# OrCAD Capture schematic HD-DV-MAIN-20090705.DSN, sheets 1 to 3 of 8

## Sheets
1 A2S- DDR2 & VOUT & GPIO: size A2
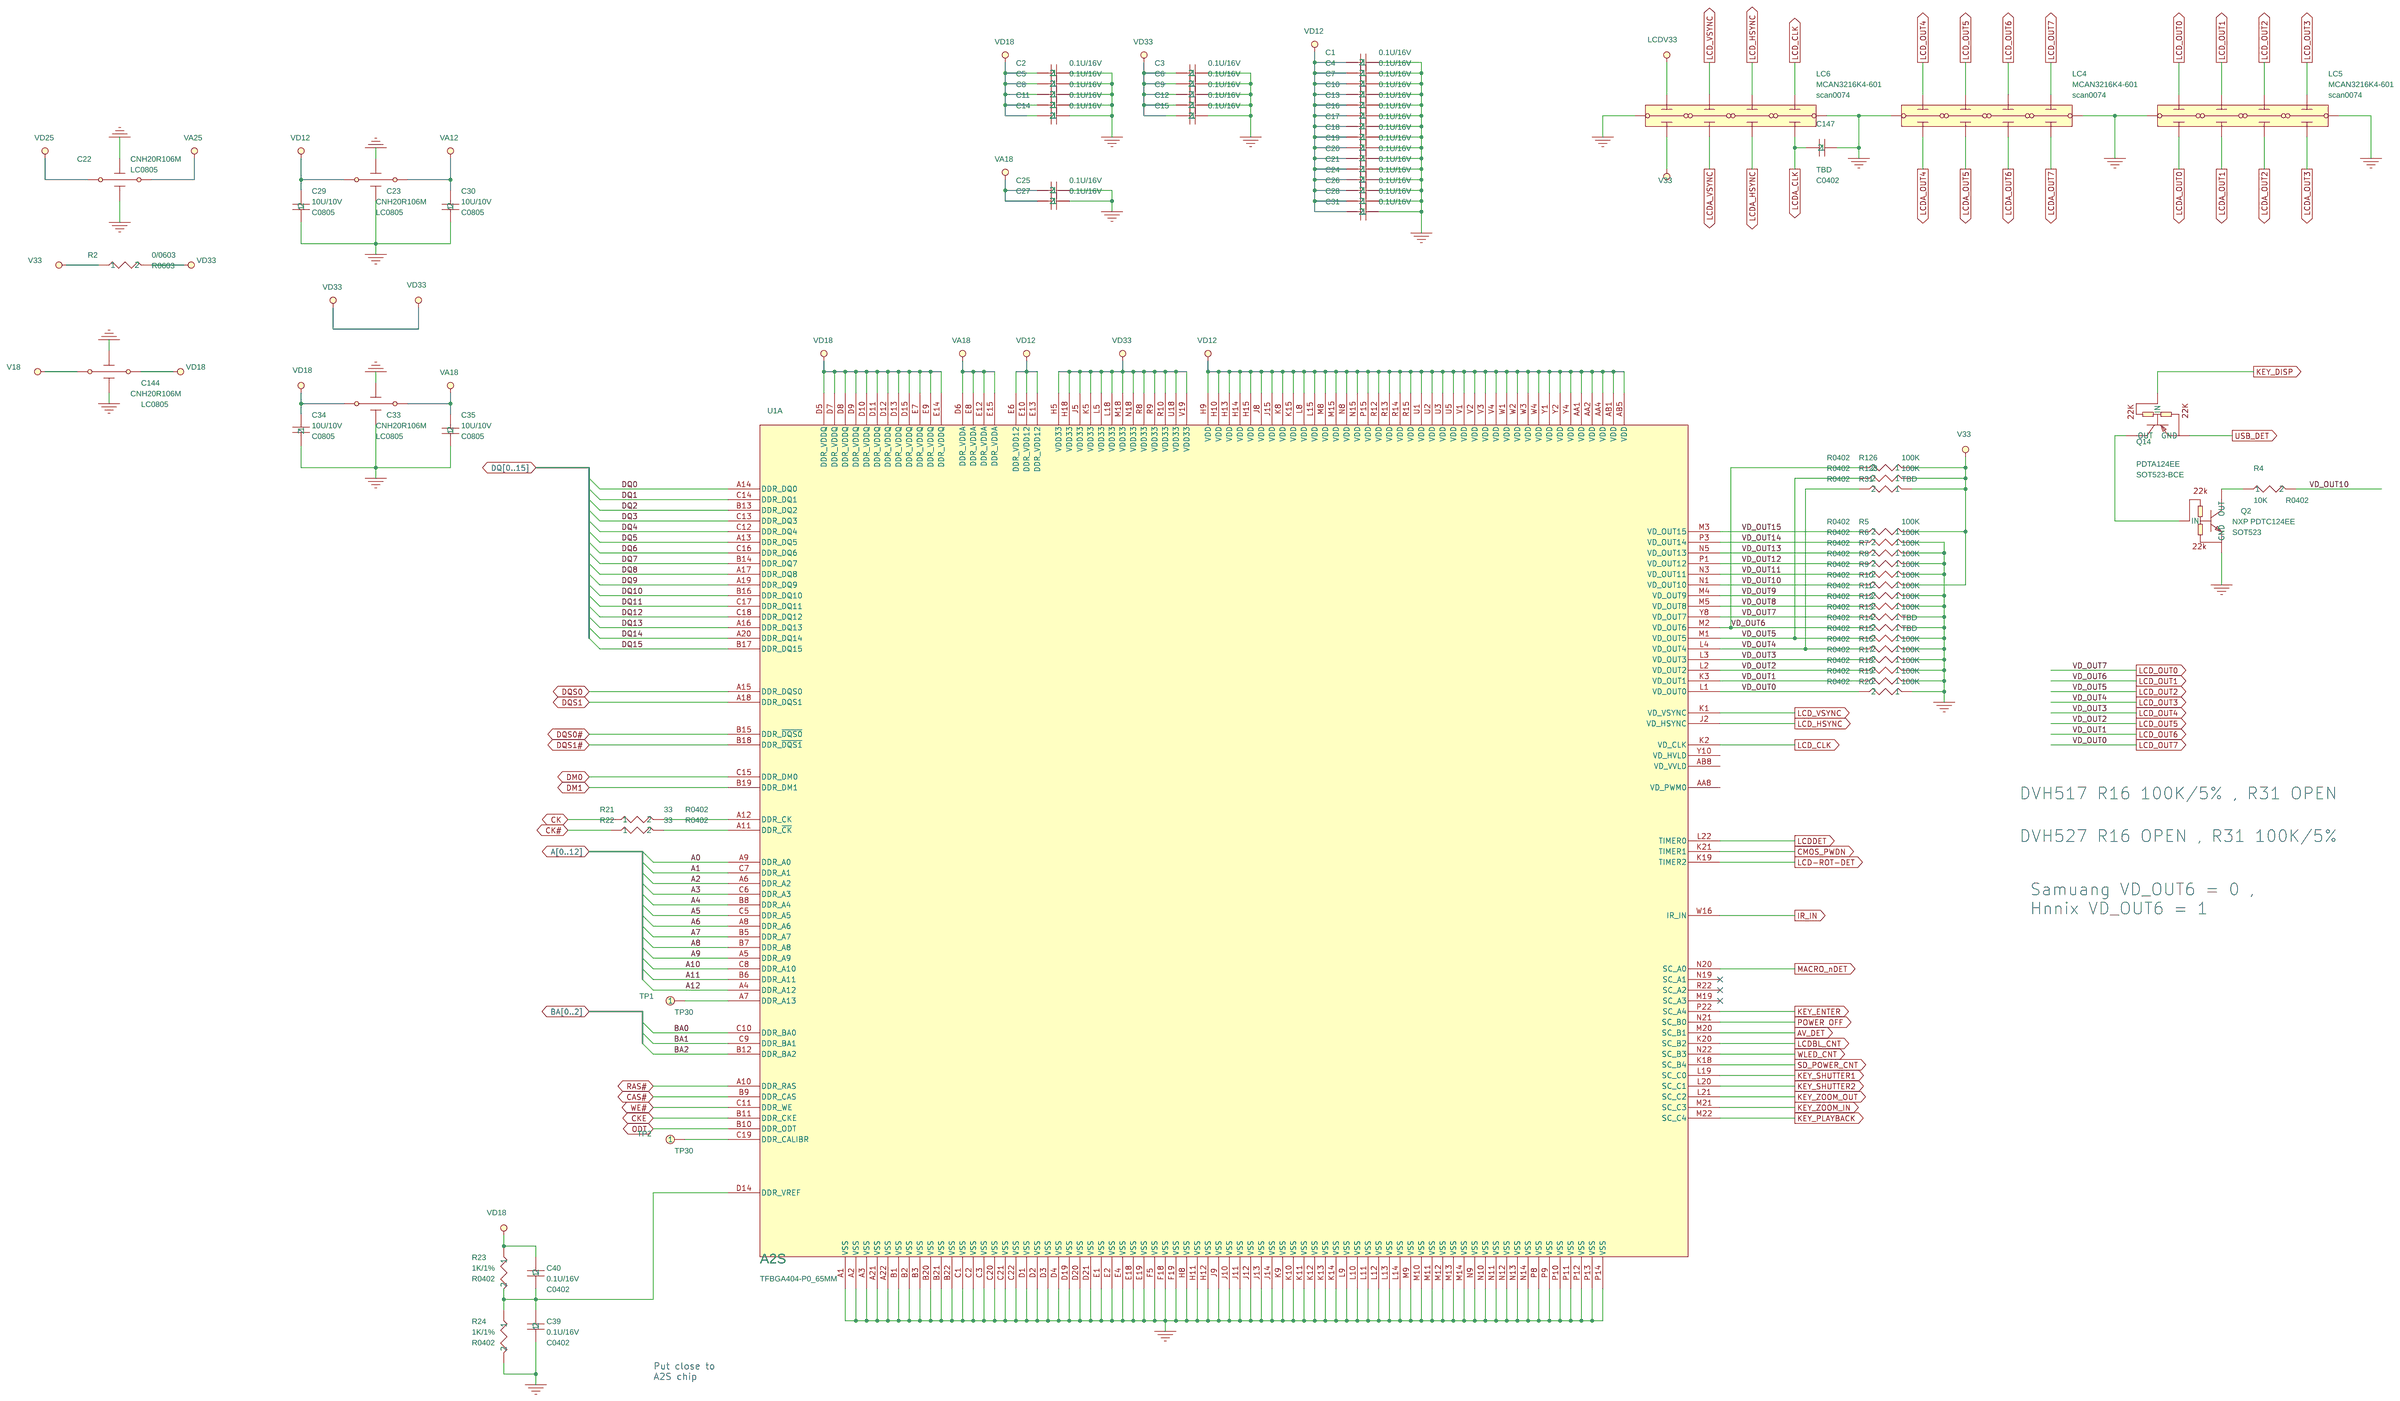
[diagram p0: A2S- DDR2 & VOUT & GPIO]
2 A2S- PWC & HDMI: size A3
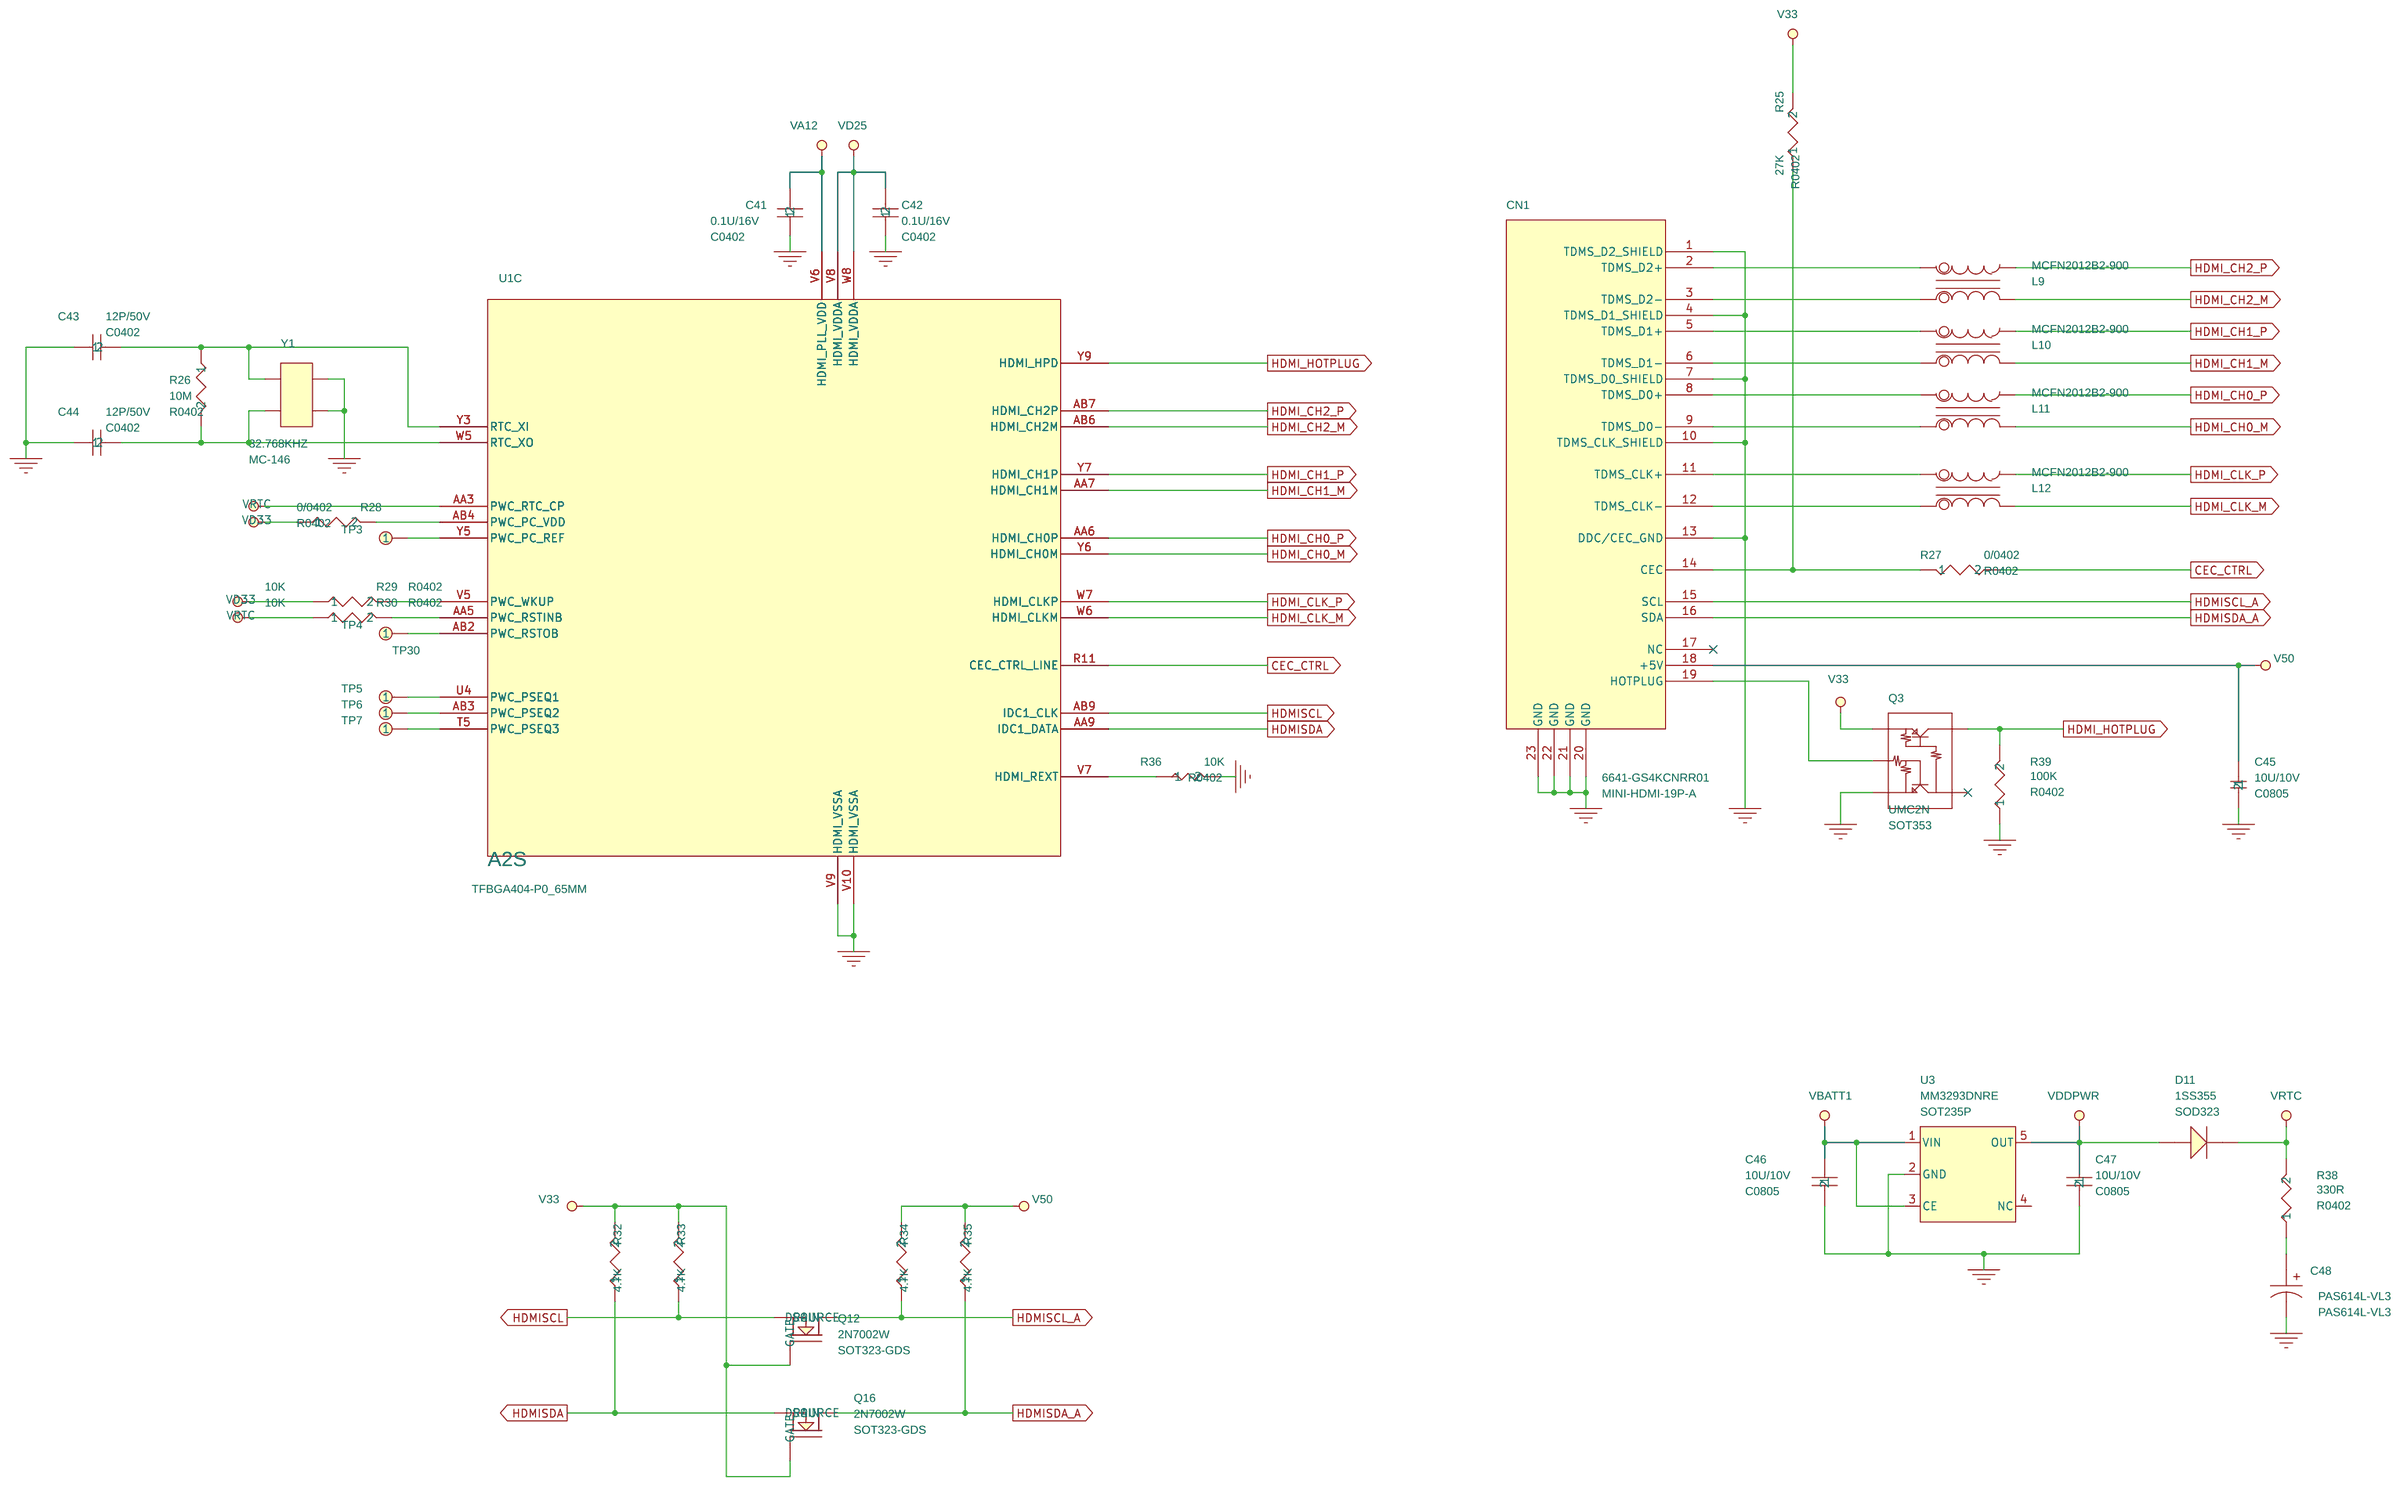
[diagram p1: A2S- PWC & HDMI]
3 A2S- SMIO & VIN& USB & Misc: size A2
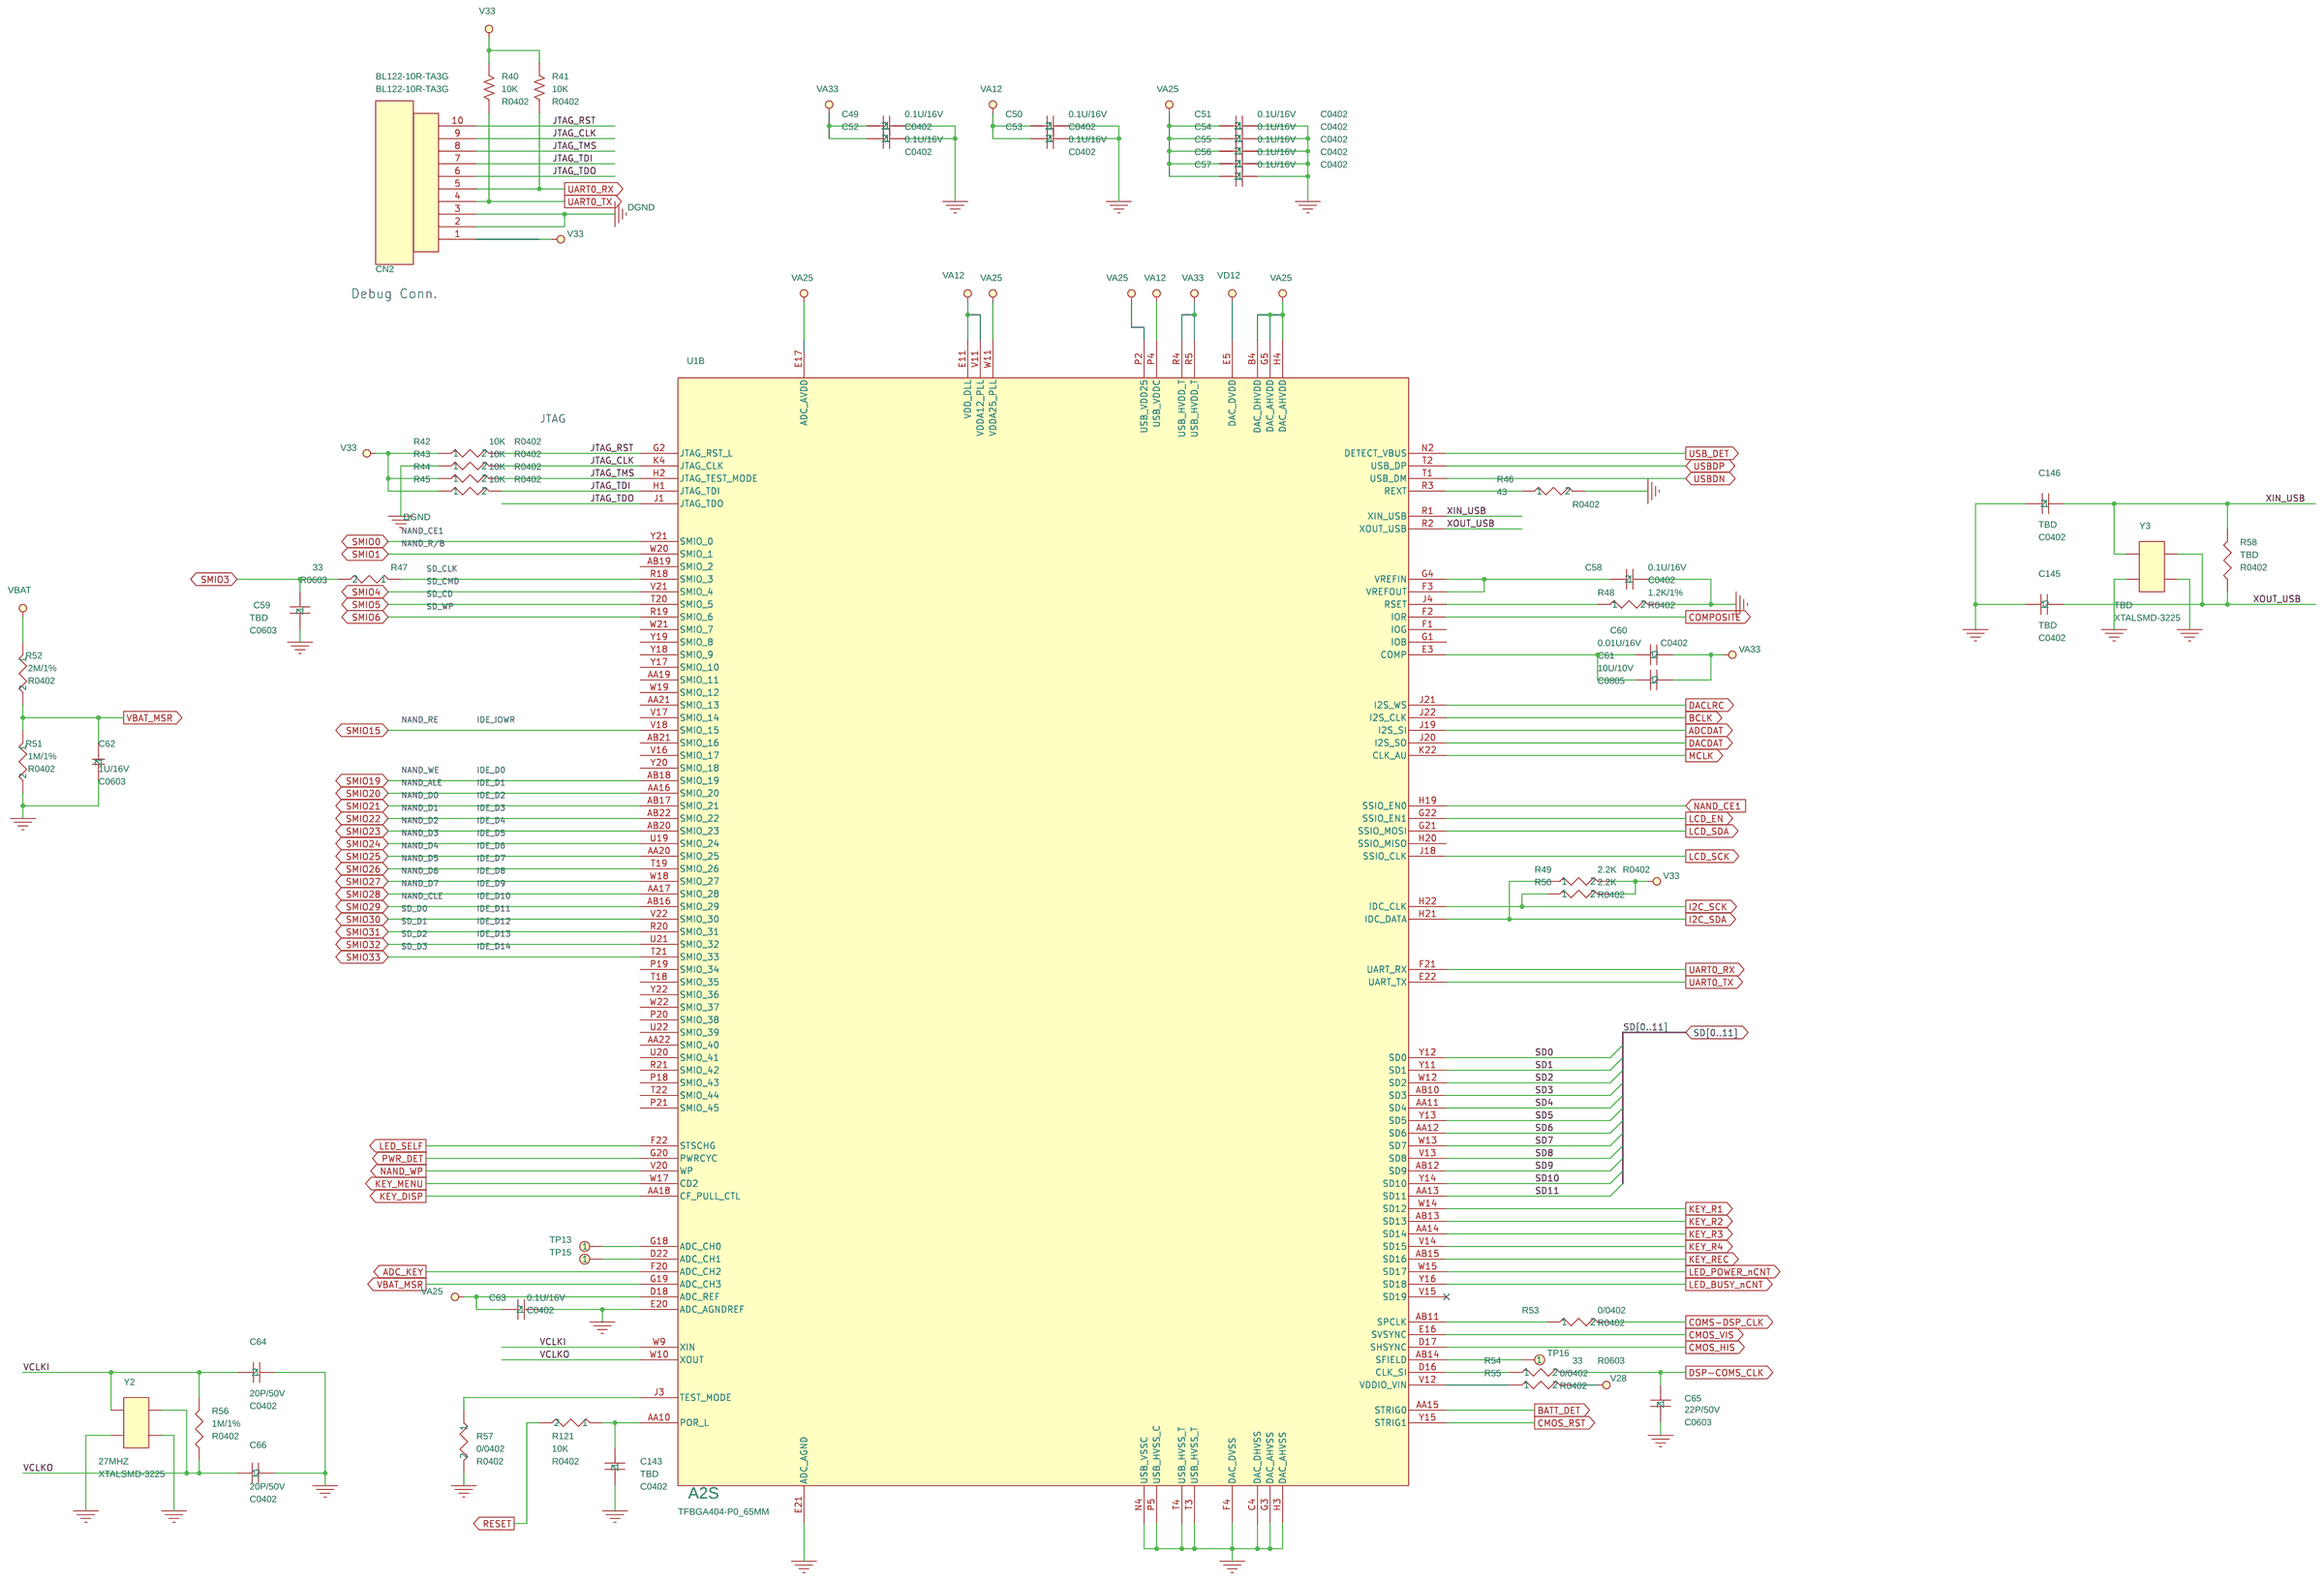
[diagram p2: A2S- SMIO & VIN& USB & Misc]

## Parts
sheet A2S- DDR2 & VOUT & GPIO
C1  0.1U/16V  [C0402]
C2  0.1U/16V  [C0402]
C3  0.1U/16V  [C0402]
C4  0.1U/16V  [C0402]
C5  0.1U/16V  [C0402]
C6  0.1U/16V  [C0402]
C7  0.1U/16V  [C0402]
C8  0.1U/16V  [C0402]
C9  0.1U/16V  [C0402]
C10  0.1U/16V  [C0402]
C11  0.1U/16V  [C0402]
C12  0.1U/16V  [C0402]
C13  0.1U/16V  [C0402]
C14  0.1U/16V  [C0402]
C15  0.1U/16V  [C0402]
C16  0.1U/16V  [C0402]
C17  0.1U/16V  [C0402]
C18  0.1U/16V  [C0402]
C19  0.1U/16V  [C0402]
C20  0.1U/16V  [C0402]
C21  0.1U/16V  [C0402]
C22  CNH20R106M  [LC0805]
C23  CNH20R106M  [LC0805]
C24  0.1U/16V  [C0402]
C25  0.1U/16V  [C0402]
C26  0.1U/16V  [C0402]
C27  0.1U/16V  [C0402]
C28  0.1U/16V  [C0402]
C29  10U/10V  [C0805]
C30  10U/10V  [C0805]
C31  0.1U/16V  [C0402]
C33  CNH20R106M  [LC0805]
C34  10U/10V  [C0805]
C35  10U/10V  [C0805]
C39  0.1U/16V  [C0402]
C40  0.1U/16V  [C0402]
C144  CNH20R106M  [LC0805]
C147  TBD  [C0402]
LC4  MCAN3216K4-601  [scan0074]
LC5  MCAN3216K4-601  [scan0074]
LC6  MCAN3216K4-601  [scan0074]
Q2  NXP PDTC124EE  [SOT523]
Q14  PDTA124EE  [SOT523-BCE]
R2  0/0603  [R0603]
R4  10K  [R0402]
R5  100K  [R0402]
R6  100K  [R0402]
R7  100K  [R0402]
R8  100K  [R0402]
R9  100K  [R0402]
R10  100K  [R0402]
R11  100K  [R0402]
R12  100K  [R0402]
R13  100K  [R0402]
R14  TBD  [R0402]
R15  TBD  [R0402]
R16  100K  [R0402]
R17  100K  [R0402]
R18  100K  [R0402]
R19  100K  [R0402]
R20  100K  [R0402]
R21  33  [R0402]
R22  33  [R0402]
R23  1K/1%  [R0402]
R24  1K/1%  [R0402]
R31  TBD  [R0402]
R123  100K  [R0402]
R126  100K  [R0402]
TP1  TP  [TP30]
TP2  TP  [TP30]
U1  A2S  [TFBGA404-P0_65MM]  (sections A,B,C)
sheet A2S- PWC & HDMI
C41  0.1U/16V  [C0402]
C42  0.1U/16V  [C0402]
C43  12P/50V  [C0402]
C44  12P/50V  [C0402]
C45  10U/10V  [C0805]
C46  10U/10V  [C0805]
C47  10U/10V  [C0805]
C48  PAS614L-VL3  [PAS614L-VL3]
CN1  6641-GS4KCNRR01  [MINI-HDMI-19P-A]
D11  1SS355  [SOD323]
L9  MCFN2012B2-900  [ACM2012]
L10  MCFN2012B2-900  [ACM2012]
L11  MCFN2012B2-900  [ACM2012]
L12  MCFN2012B2-900  [ACM2012]
Q3  UMC2N  [SOT353]
Q12  2N7002W  [SOT323-GDS]
Q16  2N7002W  [SOT323-GDS]
R25  27K  [R0402]
R26  10M  [R0402]
R27  0/0402  [R0402]
R28  0/0402  [R0402]
R29  10K  [R0402]
R30  10K  [R0402]
R32  4.7K  [R0402]
R33  4.7K  [R0402]
R34  4.7K  [R0402]
R35  4.7K  [R0402]
R36  10K  [R0402]
R38  330R  [R0402]
R39  100K  [R0402]
TP3  TP  [TP30]
TP4  TP  [TP30]
TP5  TP  [TP30]
TP6  TP  [TP30]
TP7  TP  [TP30]
U3  MM3293DNRE  [SOT235P]
Y1  32.768KHZ  [MC-146]
sheet A2S- SMIO & VIN& USB & Misc
C49  0.1U/16V  [C0402]
C50  0.1U/16V  [C0402]
C51  0.1U/16V  [C0402]
C52  0.1U/16V  [C0402]
C53  0.1U/16V  [C0402]
C54  0.1U/16V  [C0402]
C55  0.1U/16V  [C0402]
C56  0.1U/16V  [C0402]
C57  0.1U/16V  [C0402]
C58  0.1U/16V  [C0402]
C59  TBD  [C0603]
C60  0.01U/16V  [C0402]
C61  10U/10V  [C0805]
C62  1U/16V  [C0603]
C63  0.1U/16V  [C0402]
C64  20P/50V  [C0402]
C65  22P/50V  [C0603]
C66  20P/50V  [C0402]
C143  TBD  [C0402]
C145  TBD  [C0402]
C146  TBD  [C0402]
CN2  BL122-10R-TA3G  [BL122-10R-TA3G]
R40  10K  [R0402]
R41  10K  [R0402]
R42  10K  [R0402]
R43  10K  [R0402]
R44  10K  [R0402]
R45  10K  [R0402]
R46  43  [R0402]
R47  33  [R0603]
R48  1.2K/1%  [R0402]
R49  2.2K  [R0402]
R50  2.2K  [R0402]
R51  1M/1%  [R0402]
R52  2M/1%  [R0402]
R53  0/0402  [R0402]
R54  33  [R0603]
R55  0/0402  [R0402]
R56  1M/1%  [R0402]
R57  0/0402  [R0402]
R58  TBD  [R0402]
R121  10K  [R0402]
TP13  TP  [TP30]
TP15  TP  [TP30]
TP16  TP  [TP30]
Y2  27MHZ  [XTALSMD-3225]
Y3  TBD  [XTALSMD-3225]

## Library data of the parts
C1 = CAP_NP_2: CHIP CAP,104PZ/16V,0402,Y5V; Approved: Y; BOM Value: 0.1U/16V/X5R/0402; CIS_PART_NUMBER: 24-3E3-10418-000-POE; Manufacturer: POE; Manufacturer's Part Number: B0402F104ZCT; Material: Y5V; PART_TYPE: MLCC; Package Type: 0402; Part Number: 24-3E3-10418-000; Rate Volt: 16V; Tolerance: -20~+80
C2 = CAP_NP_33: CHIP CAP,104PZ/16V,0402,Y5V; Approved: Y; BOM Value: 0.1U/16V/X5R/0402; CIS_PART_NUMBER: 24-3E3-10418-000-POE; Manufacturer: POE; Manufacturer's Part Number: B0402F104ZCT; Material: Y5V; PART_TYPE: MLCC; Package Type: 0402; Part Number: 24-3E3-10418-000; Rate Volt: 16V; Tolerance: -20~+80
C3 = CAP_NP_28: CHIP CAP,104PZ/16V,0402,Y5V; Approved: Y; BOM Value: 0.1U/16V/X5R/0402; CIS_PART_NUMBER: 24-3E3-10418-000-POE; Manufacturer: POE; Manufacturer's Part Number: B0402F104ZCT; Material: Y5V; PART_TYPE: MLCC; Package Type: 0402; Part Number: 24-3E3-10418-000; Rate Volt: 16V; Tolerance: -20~+80
C4 = CAP_NP_11: CHIP CAP,104PZ/16V,0402,Y5V; Approved: Y; BOM Value: 0.1U/16V/X5R/0402; CIS_PART_NUMBER: 24-3E3-10418-000-POE; Manufacturer: POE; Manufacturer's Part Number: B0402F104ZCT; Material: Y5V; PART_TYPE: MLCC; Package Type: 0402; Part Number: 24-3E3-10418-000; Rate Volt: 16V; Tolerance: -20~+80
C5 = CAP_NP_20: CHIP CAP,104PZ/16V,0402,Y5V; Approved: Y; BOM Value: 0.1U/16V/X5R/0402; CIS_PART_NUMBER: 24-3E3-10418-000-POE; Manufacturer: POE; Manufacturer's Part Number: B0402F104ZCT; Material: Y5V; PART_TYPE: MLCC; Package Type: 0402; Part Number: 24-3E3-10418-000; Rate Volt: 16V; Tolerance: -20~+80
C6 = CAP_NP_23: CHIP CAP,104PZ/16V,0402,Y5V; Approved: Y; BOM Value: 0.1U/16V/X5R/0402; CIS_PART_NUMBER: 24-3E3-10418-000-POE; Manufacturer: POE; Manufacturer's Part Number: B0402F104ZCT; Material: Y5V; PART_TYPE: MLCC; Package Type: 0402; Part Number: 24-3E3-10418-000; Rate Volt: 16V; Tolerance: -20~+80
C7 = CAP_NP_19: CHIP CAP,104PZ/16V,0402,Y5V; Approved: Y; BOM Value: 0.1U/16V/X5R/0402; CIS_PART_NUMBER: 24-3E3-10418-000-POE; Manufacturer: POE; Manufacturer's Part Number: B0402F104ZCT; Material: Y5V; PART_TYPE: MLCC; Package Type: 0402; Part Number: 24-3E3-10418-000; Rate Volt: 16V; Tolerance: -20~+80
C8 C56 = CAP_NP_1: CHIP CAP,104PZ/16V,0402,Y5V; Approved: Y; BOM Value: 0.1U/16V/X5R/0402; CIS_PART_NUMBER: 24-3E3-10418-000-POE; Manufacturer: POE; Manufacturer's Part Number: B0402F104ZCT; Material: Y5V; PART_TYPE: MLCC; Package Type: 0402; Part Number: 24-3E3-10418-000; Rate Volt: 16V; Tolerance: -20~+80
C9 = CAP_NP_15: CHIP CAP,104PZ/16V,0402,Y5V; Approved: Y; BOM Value: 0.1U/16V/X5R/0402; CIS_PART_NUMBER: 24-3E3-10418-000-POE; Manufacturer: POE; Manufacturer's Part Number: B0402F104ZCT; Material: Y5V; PART_TYPE: MLCC; Package Type: 0402; Part Number: 24-3E3-10418-000; Rate Volt: 16V; Tolerance: -20~+80
C10 = CAP_NP_22: CHIP CAP,104PZ/16V,0402,Y5V; Approved: Y; BOM Value: 0.1U/16V/X5R/0402; CIS_PART_NUMBER: 24-3E3-10418-000-POE; Manufacturer: POE; Manufacturer's Part Number: B0402F104ZCT; Material: Y5V; PART_TYPE: MLCC; Package Type: 0402; Part Number: 24-3E3-10418-000; Rate Volt: 16V; Tolerance: -20~+80
C11 = CAP_NP_31: CHIP CAP,104PZ/16V,0402,Y5V; Approved: Y; BOM Value: 0.1U/16V/X5R/0402; CIS_PART_NUMBER: 24-3E3-10418-000-POE; Manufacturer: POE; Manufacturer's Part Number: B0402F104ZCT; Material: Y5V; PART_TYPE: MLCC; Package Type: 0402; Part Number: 24-3E3-10418-000; Rate Volt: 16V; Tolerance: -20~+80
C12 = CAP_NP_17: CHIP CAP,104PZ/16V,0402,Y5V; Approved: Y; BOM Value: 0.1U/16V/X5R/0402; CIS_PART_NUMBER: 24-3E3-10418-000-POE; Manufacturer: POE; Manufacturer's Part Number: B0402F104ZCT; Material: Y5V; PART_TYPE: MLCC; Package Type: 0402; Part Number: 24-3E3-10418-000; Rate Volt: 16V; Tolerance: -20~+80
C13 = CAP_NP_12: CHIP CAP,104PZ/16V,0402,Y5V; Approved: Y; BOM Value: 0.1U/16V/X5R/0402; CIS_PART_NUMBER: 24-3E3-10418-000-POE; Manufacturer: POE; Manufacturer's Part Number: B0402F104ZCT; Material: Y5V; PART_TYPE: MLCC; Package Type: 0402; Part Number: 24-3E3-10418-000; Rate Volt: 16V; Tolerance: -20~+80
C14 = CAP_NP_21: CHIP CAP,104PZ/16V,0402,Y5V; Approved: Y; BOM Value: 0.1U/16V/X5R/0402; CIS_PART_NUMBER: 24-3E3-10418-000-POE; Manufacturer: POE; Manufacturer's Part Number: B0402F104ZCT; Material: Y5V; PART_TYPE: MLCC; Package Type: 0402; Part Number: 24-3E3-10418-000; Rate Volt: 16V; Tolerance: -20~+80
C15 = CAP_NP_25: CHIP CAP,104PZ/16V,0402,Y5V; Approved: Y; BOM Value: 0.1U/16V/X5R/0402; CIS_PART_NUMBER: 24-3E3-10418-000-POE; Manufacturer: POE; Manufacturer's Part Number: B0402F104ZCT; Material: Y5V; PART_TYPE: MLCC; Package Type: 0402; Part Number: 24-3E3-10418-000; Rate Volt: 16V; Tolerance: -20~+80
C16 C57 = CAP_NP_13: CHIP CAP,104PZ/16V,0402,Y5V; Approved: Y; BOM Value: 0.1U/16V/X5R/0402; CIS_PART_NUMBER: 24-3E3-10418-000-POE; Manufacturer: POE; Manufacturer's Part Number: B0402F104ZCT; Material: Y5V; PART_TYPE: MLCC; Package Type: 0402; Part Number: 24-3E3-10418-000; Rate Volt: 16V; Tolerance: -20~+80
C17 C51 = CAP_NP_10: CHIP CAP,104PZ/16V,0402,Y5V; Approved: Y; BOM Value: 0.1U/16V/X5R/0402; CIS_PART_NUMBER: 24-3E3-10418-000-POE; Manufacturer: POE; Manufacturer's Part Number: B0402F104ZCT; Material: Y5V; PART_TYPE: MLCC; Package Type: 0402; Part Number: 24-3E3-10418-000; Rate Volt: 16V; Tolerance: -20~+80
C18 C54 = CAP_NP_9: CHIP CAP,104PZ/16V,0402,Y5V; Approved: Y; BOM Value: 0.1U/16V/X5R/0402; CIS_PART_NUMBER: 24-3E3-10418-000-POE; Manufacturer: POE; Manufacturer's Part Number: B0402F104ZCT; Material: Y5V; PART_TYPE: MLCC; Package Type: 0402; Part Number: 24-3E3-10418-000; Rate Volt: 16V; Tolerance: -20~+80
C19 = CAP_NP_7: CHIP CAP,104PZ/16V,0402,Y5V; Approved: Y; BOM Value: 0.1U/16V/X5R/0402; CIS_PART_NUMBER: 24-3E3-10418-000-POE; Manufacturer: POE; Manufacturer's Part Number: B0402F104ZCT; Material: Y5V; PART_TYPE: MLCC; Package Type: 0402; Part Number: 24-3E3-10418-000; Rate Volt: 16V; Tolerance: -20~+80
C20 C49 = CAP_NP_5: CHIP CAP,104PZ/16V,0402,Y5V; Approved: Y; BOM Value: 0.1U/16V/X5R/0402; CIS_PART_NUMBER: 24-3E3-10418-000-POE; Manufacturer: POE; Manufacturer's Part Number: B0402F104ZCT; Material: Y5V; PART_TYPE: MLCC; Package Type: 0402; Part Number: 24-3E3-10418-000; Rate Volt: 16V; Tolerance: -20~+80
C21 C58 = CAP_NP: CHIP CAP,104PZ/16V,0402,Y5V; Approved: Y; BOM Value: 0.1U/16V/X5R/0402; CIS_PART_NUMBER: 24-3E3-10418-000-POE; Manufacturer: POE; Manufacturer's Part Number: B0402F104ZCT; Material: Y5V; PART_TYPE: MLCC; Package Type: 0402; Part Number: 24-3E3-10418-000; Rate Volt: 16V; Tolerance: -20~+80
C22 C23 C33 C144 = CAPACITOR_FEED_5
C24 = CAP_NP_30: CHIP CAP,104PZ/16V,0402,Y5V; Approved: Y; BOM Value: 0.1U/16V/X5R/0402; CIS_PART_NUMBER: 24-3E3-10418-000-POE; Manufacturer: POE; Manufacturer's Part Number: B0402F104ZCT; Material: Y5V; PART_TYPE: MLCC; Package Type: 0402; Part Number: 24-3E3-10418-000; Rate Volt: 16V; Tolerance: -20~+80
C25 C63 = CAP_NP_8: CHIP CAP,104PZ/16V,0402,Y5V; Approved: Y; BOM Value: 0.1U/16V/X5R/0402; CIS_PART_NUMBER: 24-3E3-10418-000-POE; Manufacturer: POE; Manufacturer's Part Number: B0402F104ZCT; Material: Y5V; PART_TYPE: MLCC; Package Type: 0402; Part Number: 24-3E3-10418-000; Rate Volt: 16V; Tolerance: -20~+80
C26 = CAP_NP_29: CHIP CAP,104PZ/16V,0402,Y5V; Approved: Y; BOM Value: 0.1U/16V/X5R/0402; CIS_PART_NUMBER: 24-3E3-10418-000-POE; Manufacturer: POE; Manufacturer's Part Number: B0402F104ZCT; Material: Y5V; PART_TYPE: MLCC; Package Type: 0402; Part Number: 24-3E3-10418-000; Rate Volt: 16V; Tolerance: -20~+80
C27 = CAP_NP_14: CHIP CAP,104PZ/16V,0402,Y5V; Approved: Y; BOM Value: 0.1U/16V/X5R/0402; CIS_PART_NUMBER: 24-3E3-10418-000-POE; Manufacturer: POE; Manufacturer's Part Number: B0402F104ZCT; Material: Y5V; PART_TYPE: MLCC; Package Type: 0402; Part Number: 24-3E3-10418-000; Rate Volt: 16V; Tolerance: -20~+80
C28 = CAP_NP_27: CHIP CAP,104PZ/16V,0402,Y5V; Approved: Y; BOM Value: 0.1U/16V/X5R/0402; CIS_PART_NUMBER: 24-3E3-10418-000-POE; Manufacturer: POE; Manufacturer's Part Number: B0402F104ZCT; Material: Y5V; PART_TYPE: MLCC; Package Type: 0402; Part Number: 24-3E3-10418-000; Rate Volt: 16V; Tolerance: -20~+80
C29 = CAP_NP_18: BOM Value: 10U/10V/X5R/0805
C30 = CAP_NP_6: BOM Value: 10U/10V/X5R/0805
C31 = CAP_NP_24: CHIP CAP,104PZ/16V,0402,Y5V; Approved: Y; BOM Value: 0.1U/16V/X5R/0402; CIS_PART_NUMBER: 24-3E3-10418-000-POE; Manufacturer: POE; Manufacturer's Part Number: B0402F104ZCT; Material: Y5V; PART_TYPE: MLCC; Package Type: 0402; Part Number: 24-3E3-10418-000; Rate Volt: 16V; Tolerance: -20~+80
C34 = CAP_NP_32: BOM Value: 10U/10V/X5R/0805
C35 = CAP_NP_4: BOM Value: 10U/10V/X5R/0805
C39 = CAP_NP_26: CHIP CAP,104PZ/16V,0402,Y5V; Approved: Y; BOM Value: 0.1U/16V/X5R/0402; CIS_PART_NUMBER: 24-3E3-10418-000-POE; Manufacturer: POE; Manufacturer's Part Number: B0402F104ZCT; Material: Y5V; PART_TYPE: MLCC; Package Type: 0402; Part Number: 24-3E3-10418-000; Rate Volt: 16V; Tolerance: -20~+80
C40 C42 C55 = CAP_NP_3: CHIP CAP,104PZ/16V,0402,Y5V; Approved: Y; BOM Value: 0.1U/16V/X5R/0402; CIS_PART_NUMBER: 24-3E3-10418-000-POE; Manufacturer: POE; Manufacturer's Part Number: B0402F104ZCT; Material: Y5V; PART_TYPE: MLCC; Package Type: 0402; Part Number: 24-3E3-10418-000; Rate Volt: 16V; Tolerance: -20~+80
C147 = CAP_NP_16: CHIP CAP,104PZ/16V,0402,Y5V; Approved: Y; CIS_PART_NUMBER: 24-3E3-10418-000-POE; Manufacturer: POE; Manufacturer's Part Number: B0402F104ZCT; Material: Y5V; PART_TYPE: MLCC; Package Type: 0402; Part Number: 24-3E3-10418-000; Rate Volt: 16V; Tolerance: -20~+80
LC4 LC5 = CAPACITOR_FEED_11
LC6 = CAPACITOR_FEED_11: BOM Value: CNA30C221M-BM
Q2 = NPN_0
Q14 = NPN_4
R2 = R_v2_3: CHIP RES,33ohm,0402 J; Approved: Y; BOM Value: 0/5%/0603; CIS_PART_NUMBER: 20-116-33006-000-RALEC; Manufacturer: RALEC; Manufacturer's Part Number: RTT02330JTP; PART_TYPE: CHIP RES; Package Type: 0402; Part Number: 20-116-33006-000; Tolerance: 5%; W: 1/16W
R4 = R_v2_19: CHIP RES,10K,0402 J; Approved: Y; BOM Value: 10K/5%/0402; CIS_PART_NUMBER: 20-116-10306-000-RALEC; Manufacturer: RALEC; Manufacturer's Part Number: RTT02103JTP; PART_TYPE: CHIP RES; Package Type: 0402; Part Number: 20-116-10306-000; Tolerance: 5%; W: 1/16W
R5 = R_v2_5: BOM Value: 100K/5%/0402
R6 = R_v2_18: BOM Value: 100K/5%/0402
R7 = R_v2_14: BOM Value: 100K/5%/0402
R8 = R_v2_22: BOM Value: 100K/5%/0402
R9 = R_v2_10: BOM Value: 100K/5%/0402
R10 = R_v2_8: BOM Value: 100K/5%/0402
R11 = R_v2_11: BOM Value: 100K/5%/0402
R12 = R_v2: BOM Value: 100K/5%/0402
R13 = R_v2_20: BOM Value: 100K/5%/0402
R14 = R_v2_9
R15 = R_v2_21
R16 = R_v2_4: BOM Value: 100K/5%/0402
R17 = R_v2_13: BOM Value: 100K/5%/0402
R18 = R_v2_12: BOM Value: 100K/5%/0402
R19 = R_v2_1: BOM Value: 100K/5%/0402
R20 = R_v2_7: BOM Value: 100K/5%/0402
R21 = R_v2_17: CHIP RES,33ohm,0402 J; Approved: Y; BOM Value: 33/5%/0402; CIS_PART_NUMBER: 20-116-33006-000-RALEC; Manufacturer: RALEC; Manufacturer's Part Number: RTT02330JTP; PART_TYPE: CHIP RES; Package Type: 0402; Part Number: 20-116-33006-000; Tolerance: 5%; W: 1/16W
R22 = R_v2_16: CHIP RES,33ohm,0402 J; Approved: Y; BOM Value: 33/5%/0402; CIS_PART_NUMBER: 20-116-33006-000-RALEC; Manufacturer: RALEC; Manufacturer's Part Number: RTT02330JTP; PART_TYPE: CHIP RES; Package Type: 0402; Part Number: 20-116-33006-000; Tolerance: 5%; W: 1/16W
R23 = R_v2_15: CHIP RES,1K,0402 F; Approved: Y; BOM Value: 1K/1%/0402; CIS_PART_NUMBER: 20-266-10010-000-RALEC; Manufacturer: RALEC; Manufacturer's Part Number: RTT021001FTP; PART_TYPE: CHIP RES; Package Type: 0402; Part Number: 20-266-10010-000; Tolerance: 1%; W: 1/16W
R24 = R_v2_24: CHIP RES,1K,0402 F; Approved: Y; BOM Value: 1K/1%/0402; CIS_PART_NUMBER: 20-266-10010-000-RALEC; Manufacturer: RALEC; Manufacturer's Part Number: RTT021001FTP; PART_TYPE: CHIP RES; Package Type: 0402; Part Number: 20-266-10010-000; Tolerance: 1%; W: 1/16W
R31 = R_v2_2
R123 = R_v2_23: BOM Value: 100K/5%/0402
R126 = R_v2_6: BOM Value: 100K/5%/0402
TP1-TP7 TP13 TP15 TP16 = POINT_2: 8TH PART FIELD: PADR60
U1 = A2S_2
C41 C53 = CAP_NP_4: CHIP CAP,104PZ/16V,0402,Y5V; Approved: Y; BOM Value: 0.1U/16V/X5R/0402; CIS_PART_NUMBER: 24-3E3-10418-000-POE; Manufacturer: POE; Manufacturer's Part Number: B0402F104ZCT; Material: Y5V; PART_TYPE: MLCC; Package Type: 0402; Part Number: 24-3E3-10418-000; Rate Volt: 16V; Tolerance: -20~+80
C43 = CAP_NP_5: BOM Value: 12P/50V/NPO/0402
C44 = CAP_NP_1: BOM Value: 12P/50V/NPO/0402
C45 = CAP_CERAMIC_0: BOM Value: 10U/10V/X5R/0805
C46 = CAP_NP_2: BOM Value: 10U/10V/X5R/0805
C47 = CAP_NP: BOM Value: 10U/10V/X5R/0805
C48 = CAP_POL: GOLD CAP
CN1 = HDMI_TYPE_A_3: CONN. HDMI TO PCB RA SMD 90D MOLEX 500254-1927; MFR: MOLEX; Package: ZP00076; ZPN: SECNG0125
D11 = DIODE: DIODE,SW,1SS355,UMD2,80V,1.2V,225mA,90V; Approved: Y; CIS_PART_NUMBER: 01-02B-00001-000-ROHM; Index1: VF=1.2V-100mA; Index2: IF=100mA; Index3: VR=80V; Manufacturer: ROHM; Package Type: UMD2; Part Number: 01-02B-00001-000
L9-L12 = SF0905_0: Vender: °ª³Ð
Q3 = UMC2N: Vendor: ROHM
Q12 Q16 = MOSFET_N_2
R25 = R_v2_5: BOM Value: 27K/5%/0402
R26 = R_v2_10: CHIP RES,75ohm,0402 F; Approved: Y; BOM Value: 10M/5%/0402; CIS_PART_NUMBER: 20-266-07500-000-RALEC; Manufacturer: RALEC; Manufacturer's Part Number: RTT020750FTP; PART_TYPE: CHIP RES; Package Type: 0402; Part Number: 20-266-07500-000; Tolerance: 1%; W: 1/16W
R27 = R_v2_3: BOM Value: 0/5%/0402
R28 = R_v2_9: CHIP RES,10K,0402 J; Approved: Y; BOM Value: 0/5%/0402; CIS_PART_NUMBER: 20-116-10306-000-RALEC; Manufacturer: RALEC; Manufacturer's Part Number: RTT02103JTP; PART_TYPE: CHIP RES; Package Type: 0402; Part Number: 20-116-10306-000; Tolerance: 5%; W: 1/16W
R29 = R_v2_4: CHIP RES,10K,0402 J; Approved: Y; BOM Value: 10K/5%/0402; CIS_PART_NUMBER: 20-116-10306-000-RALEC; Manufacturer: RALEC; Manufacturer's Part Number: RTT02103JTP; PART_TYPE: CHIP RES; Package Type: 0402; Part Number: 20-116-10306-000; Tolerance: 5%; W: 1/16W
R30 = R_v2_1: CHIP RES,10K,0402 J; Approved: Y; BOM Value: 10K/5%/0402; CIS_PART_NUMBER: 20-116-10306-000-RALEC; Manufacturer: RALEC; Manufacturer's Part Number: RTT02103JTP; PART_TYPE: CHIP RES; Package Type: 0402; Part Number: 20-116-10306-000; Tolerance: 5%; W: 1/16W
R32 = R_v2: BOM Value: 4.7K/5%/0402
R33 = R_v2_11: BOM Value: 4.7K/5%/0402
R34 = R_v2_6: BOM Value: 4.7K/5%/0402
R35 = R_v2_8: BOM Value: 4.7K/5%/0402
R36 = R_v3: BOM Value: 10K/5%/0402
R38 = R_v2_7: CHIP RES,33ohm,0402 J; Approved: Y; BOM Value: 330R/5%/0402; CIS_PART_NUMBER: 20-116-33006-000-RALEC; Manufacturer: RALEC; Manufacturer's Part Number: RTT02330JTP; PART_TYPE: CHIP RES; Package Type: 0402; Part Number: 20-116-33006-000; Tolerance: 5%; W: 1/16W
R39 = R_v2_2: CHIP RES,33ohm,0402 J; Approved: Y; BOM Value: 100K/5%/0402; CIS_PART_NUMBER: 20-116-33006-000-RALEC; Manufacturer: RALEC; Manufacturer's Part Number: RTT02330JTP; PART_TYPE: CHIP RES; Package Type: 0402; Part Number: 20-116-33006-000; Tolerance: 5%; W: 1/16W
U3 = AT1202_3
Y1 = RS_CRYSTAL_1: BOM Value: 32.768KHZ/NC26
C50 = CAP_NP_16: CHIP CAP,104PZ/16V,0402,Y5V; Approved: Y; BOM Value: 0.1U/16V/X5R/0402; CIS_PART_NUMBER: 24-3E3-10418-000-POE; Manufacturer: POE; Manufacturer's Part Number: B0402F104ZCT; Material: Y5V; PART_TYPE: MLCC; Package Type: 0402; Part Number: 24-3E3-10418-000; Rate Volt: 16V; Tolerance: -20~+80
C52 = CAP_NP_6: CHIP CAP,104PZ/16V,0402,Y5V; Approved: Y; BOM Value: 0.1U/16V/X5R/0402; CIS_PART_NUMBER: 24-3E3-10418-000-POE; Manufacturer: POE; Manufacturer's Part Number: B0402F104ZCT; Material: Y5V; PART_TYPE: MLCC; Package Type: 0402; Part Number: 24-3E3-10418-000; Rate Volt: 16V; Tolerance: -20~+80
C59 = CAP_NP_11: CHIP CAP,22PJ/50V,0402,NPO; Approved: Y; CIS_PART_NUMBER: 24-3E0-22045-000-POE; Manufacturer: POE; Manufacturer's Part Number: U0402C220JCT; Material: NPO; PART_TYPE: MLCC; Package Type: 0402; Part Number: 24-3E0-22045-000; Rate Volt: 50V; Tolerance: +-5%
C60 = CAP_NP_17: CHIP CAP,103PK/10V,0402,X7R; Approved: Y; BOM Value: 0.01U/16V/X5R/0402; CIS_PART_NUMBER: 24-3E1-10306-000-HEC; Manufacturer: HEC; Manufacturer's Part Number: C0402X103K100T; Material: X7R; PART_TYPE: MLCC; Package Type: 0402; Part Number: 24-3E1-10306-000; Rate Volt: 10V; Tolerance: +-10%
C61 = CAP_NP_19: CHIP CAP,106PK/10V,0805,X5R; Approved: Y; BOM Value: 10U/10V/X5R/0805; CIS_PART_NUMBER: 24-3A5-10606-000-TAIYO YUDEN; Manufacturer: TAIYO YUDEN; Manufacturer's Part Number: LMK212BJ106KG; Material: X5R; PART_TYPE: MLCC; Package Type: 0805; Part Number: 24-3A5-10606-000; Rate Volt: 10V; Tolerance: 10%
C62 = CAP_CERAMIC_0: BOM Value: 1U/16V/X5R/0603
C64 = CAP_NP_14: BOM Value: 20P/50V/NPO/0402
C65 = CAP_NP_2: CHIP CAP,22PJ/50V,0402,NPO; Approved: Y; BOM Value: 22P/50V/NPO/0603; CIS_PART_NUMBER: 24-3E0-22045-000-POE; Manufacturer: POE; Manufacturer's Part Number: U0402C220JCT; Material: NPO; PART_TYPE: MLCC; Package Type: 0402; Part Number: 24-3E0-22045-000; Rate Volt: 50V; Tolerance: +-5%
C66 = CAP_NP_12: NPO; BOM Value: 20P/50V/NPO/0402
C143 = CAP_NP_7: CHIP CAP,104PZ/16V,0402,Y5V; Approved: Y; CIS_PART_NUMBER: 24-3E3-10418-000-POE; Manufacturer: POE; Manufacturer's Part Number: B0402F104ZCT; Material: Y5V; PART_TYPE: MLCC; Package Type: 0402; Part Number: 24-3E3-10418-000; Rate Volt: 16V; Tolerance: -20~+80
C145 = CAP_NP_15
C146 = CAP_NP_18: NPO
CN2 = FPC_CON24P_1: Vender: ®¦±o§Q; Vendor: ®¦±o§Q
R40 = R: BOM Value: 10K/5%/0402
R41 = R_1: BOM Value: 10K/5%/0402
R42 = R_v2_11: CHIP RES,10K,0402 J; Approved: Y; BOM Value: 10K/5%/0402; CIS_PART_NUMBER: 20-116-10306-000-RALEC; Manufacturer: RALEC; Manufacturer's Part Number: RTT02103JTP; PART_TYPE: CHIP RES; Package Type: 0402; Part Number: 20-116-10306-000; Tolerance: 5%; W: 1/16W
R43 = R_v2_7: CHIP RES,10K,0402 J; Approved: Y; BOM Value: 10K/5%/0402; CIS_PART_NUMBER: 20-116-10306-000-RALEC; Manufacturer: RALEC; Manufacturer's Part Number: RTT02103JTP; PART_TYPE: CHIP RES; Package Type: 0402; Part Number: 20-116-10306-000; Tolerance: 5%; W: 1/16W
R44 = R_v2_3: CHIP RES,10K,0402 J; Approved: Y; BOM Value: 10K/5%/0402; CIS_PART_NUMBER: 20-116-10306-000-RALEC; Manufacturer: RALEC; Manufacturer's Part Number: RTT02103JTP; PART_TYPE: CHIP RES; Package Type: 0402; Part Number: 20-116-10306-000; Tolerance: 5%; W: 1/16W
R45 = R_v2_15: CHIP RES,10K,0402 J; Approved: Y; BOM Value: 10K/5%/0402; CIS_PART_NUMBER: 20-116-10306-000-RALEC; Manufacturer: RALEC; Manufacturer's Part Number: RTT02103JTP; PART_TYPE: CHIP RES; Package Type: 0402; Part Number: 20-116-10306-000; Tolerance: 5%; W: 1/16W
R46 = R_v2_12: CHIP RES,3.4K,0402F; Approved: Y; BOM Value: 43/5%/0402; CIS_PART_NUMBER: 20-266-34010-000-TMTEC; Manufacturer: TMTEC; Manufacturer's Part Number: CR02FL63K4; PART_TYPE: CHIP RES; Package Type: 0402; Part Number: 20-266-34010-000; Tolerance: 1%; W: 1/16W
R47 = R_v2_9: CHIP RES,33ohm,0402 J; Approved: Y; BOM Value: 33/5%/0603; CIS_PART_NUMBER: 20-116-33006-000-RALEC; Manufacturer: RALEC; Manufacturer's Part Number: RTT02330JTP; PART_TYPE: CHIP RES; Package Type: 0402; Part Number: 20-116-33006-000; Tolerance: 5%; W: 1/16W
R48 = R_v2_10: CHIP RES,1.37K,0402 F; Approved: Y; BOM Value: 1.2K/1%/0402; CIS_PART_NUMBER: 20-266-13710-000-TMTEC; Manufacturer: TMTEC; Manufacturer's Part Number: CR-02FL7--1K37; PART_TYPE: CHIP RES; Package Type: 0402; Part Number: 20-266-13710-000; Tolerance: 1%; W: 1/16W
R49 = R_v2_14: CHIP RES,1.5K,0402 J; Approved: Y; BOM Value: 2.2K/5%/0402; CIS_PART_NUMBER: 20-116-15206-000-RALEC; Manufacturer: RALEC; Manufacturer's Part Number: RTT02152JTP; PART_TYPE: CHIP RES; Package Type: 0402; Part Number: 20-116-15206-000; Tolerance: 5%; W: 1/16W
R50 = R_v2_13: CHIP RES,1.5K,0402 J; Approved: Y; BOM Value: 2.2K/5%/0402; CIS_PART_NUMBER: 20-116-15206-000-RALEC; Manufacturer: RALEC; Manufacturer's Part Number: RTT02152JTP; PART_TYPE: CHIP RES; Package Type: 0402; Part Number: 20-116-15206-000; Tolerance: 5%; W: 1/16W
R51 = R_v2_6: BOM Value: 1M/1%/0402
R52 = R_v2_1: BOM Value: 2M/1%/0402
R53 = R_v2_8: CHIP RES,0ohm,0402 J; Approved: Y; BOM Value: 0/5%/0402; CIS_PART_NUMBER: 20-116-00006-000-RALEC; Manufacturer: RALEC; Manufacturer's Part Number: RTT02000JTP; PART_TYPE: CHIP RES; Package Type: 0402; Part Number: 20-116-00006-000; Tolerance: 5%; W: 1/10W
R54 = R_v2_5: CHIP RES,33ohm,0402 J; Approved: Y; BOM Value: 33/5%/0603; CIS_PART_NUMBER: 20-116-33006-000-RALEC; Manufacturer: RALEC; Manufacturer's Part Number: RTT02330JTP; PART_TYPE: CHIP RES; Package Type: 0402; Part Number: 20-116-33006-000; Tolerance: 5%; W: 1/16W
R55 = R_v2_4: CHIP RES,33ohm,0402 J; Approved: Y; BOM Value: 0/5%/0402; CIS_PART_NUMBER: 20-116-33006-000-RALEC; Manufacturer: RALEC; Manufacturer's Part Number: RTT02330JTP; PART_TYPE: CHIP RES; Package Type: 0402; Part Number: 20-116-33006-000; Tolerance: 5%; W: 1/16W
R56 = R_0: BOM Value: 1M/1%/0402
R57 = R_v2_2: CHIP RES,0ohm,0402 J; Approved: Y; BOM Value: 0/5%/0402; CIS_PART_NUMBER: 20-116-00006-000-RALEC; Manufacturer: RALEC; Manufacturer's Part Number: RTT02000JTP; PART_TYPE: CHIP RES; Package Type: 0402; Part Number: 20-116-00006-000; Tolerance: 5%; W: 1/10W
R58 = R_0
R121 = R_v2: BOM Value: 10K/5%/0402
Y2 = RS_CRYSTAL_2
Y3 = RS_CRYSTAL_1

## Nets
DGND: C1.1 C2.1 C3.1 C4.1 C5.1 C6.1 C7.1 C8.1 C9.1 C10.1 C11.1 C12.1 C13.1 C14.1 C15.1 C16.1 C17.1 C18.1 C19.1 C20.1 C21.1 C22.C(GND) C22.D(GND) C23.C(GND) C23.D(GND) C24.1 C25.1 C26.1 C27.1 C28.1 C29.1 C30.1 C31.1 C33.C(GND) C33.D(GND) C34.2 C35.1 C39.1 C41.1 C42.1 C43.1 C44.1 C45.2 C46.2 C47.2 C48.2 C49.1 C50.1 C51.1 C52.1 C53.1 C54.1 C55.1 C56.1 C57.1 C58.1 C59.2 C62.2 C63.1 C64.1 C65.2 C66.2 C143.2 C144.C(GND) C144.D(GND) C145.1 C146.2 C147.1 CN1.1(TDMS_D2_SHIELD) CN1.4(TDMS_D1_SHIELD) CN1.7(TDMS_D0_SHIELD) CN1.10(TDMS_CLK_SHIELD) CN1.13(DDC/CEC_GND) CN1.20(GND) CN1.21(GND) CN1.22(GND) CN1.23(GND) CN2.2 CN2.3 LC4.I(GND) LC4.J(GND) LC5.I(GND) LC5.J(GND) LC6.I(GND) LC6.J(GND) Q2.3(GND) Q3.1 R6.1 R7.1 R8.1 R9.1 R11.1 R12.1 R13.1 R14.1 R15.1 R16.1 R17.1 R18.1 R19.1 R20.1 R24.2 R36.2 R39.1 R43.1 R46.2 R48.2 R51.2 R57.2 U1.A1(VSS) U1.A2(VSS) U1.A3(VSS) U1.A21(VSS) U1.A22(VSS) U1.B1(VSS) U1.B2(VSS) U1.B3(VSS) U1.B20(VSS) U1.B21(VSS) U1.B22(VSS) U1.C1(VSS) U1.C2(VSS) U1.C3(VSS) U1.C4(DAC_DHVSS) U1.C20(VSS) U1.C21(VSS) U1.C22(VSS) U1.D1(VSS) U1.D2(VSS) U1.D3(VSS) U1.D4(VSS) U1.D19(VSS) U1.D20(VSS) U1.D21(VSS) U1.E1(VSS) U1.E2(VSS) U1.E4(VSS) U1.E18(VSS) U1.E19(VSS) U1.E20(ADC_AGNDREF) U1.E21(ADC_AGND) U1.F4(DAC_DVSS) U1.F5(VSS) U1.F18(VSS) U1.F19(VSS) U1.G3(DAC_AHVSS) U1.H3(DAC_AHVSS) U1.H8(VSS) U1.H11(VSS) U1.H12(VSS) U1.J9(VSS) U1.J10(VSS) U1.J11(VSS) U1.J12(VSS) U1.J13(VSS) U1.J14(VSS) U1.K9(VSS) U1.K10(VSS) U1.K11(VSS) U1.K12(VSS) U1.K13(VSS) U1.K14(VSS) U1.L9(VSS) U1.L10(VSS) U1.L11(VSS) U1.L12(VSS) U1.L13(VSS) U1.L14(VSS) U1.M9(VSS) U1.M10(VSS) U1.M11(VSS) U1.M12(VSS) U1.M13(VSS) U1.M14(VSS) U1.N4(USB_VSSC) U1.N9(VSS) U1.N10(VSS) U1.N11(VSS) U1.N12(VSS) U1.N13(VSS) U1.N14(VSS) U1.P5(USB_HVSS_C) U1.P8(VSS) U1.P9(VSS) U1.P10(VSS) U1.P11(VSS) U1.P12(VSS) U1.P13(VSS) U1.P14(VSS) U1.T3(USB_HVSS_T) U1.T4(USB_HVSS_T) U1.V9(HDMI_VSSA) U1.V10(HDMI_VSSA) U3.2(GND) Y1.2 Y1.3 Y2.2 Y2.4 Y3.2 Y3.4 ; also on sheet 4 5 6 7 8
V18: C144.A(IN) ; also on sheet 4 5 7
V28: R55.2 ; also on sheet 4
V33: CN2.1 LC6.D(IN) Q3.3 Q12.G(GATE) Q16.G(GATE) R2.1 R5.1 R10.1 R25.2 R31.1 R32.2 R33.2 R40.2 R41.2 R42.1 R44.1 R45.1 R49.2 R50.2 R123.1 R126.1 ; also on sheet 4 6 7 8
V50: C45.1 CN1.18(+5V) R34.2 R35.2 ; also on sheet 7 8
VBAT: R52.1 ; also on sheet 7
VBAT_MSR: C62.1 R51.1 R52.2 U1.G19(ADC_CH3)
VBATT1: C46.1 U3.1(VIN) U3.3(CE) ; also on sheet 7
VDDPWR: C47.1 D11.A U3.5(OUT) ; also on sheet 4 7
A0: U1.A9(DDR_A0) ; also on sheet 5
A1: U1.C7(DDR_A1) ; also on sheet 5
A2: U1.A6(DDR_A2) ; also on sheet 5
A3: U1.C6(DDR_A3) ; also on sheet 5
A4: U1.B8(DDR_A4) ; also on sheet 5
A5: U1.C5(DDR_A5) ; also on sheet 5
A6: U1.A8(DDR_A6) ; also on sheet 5
A7: U1.B5(DDR_A7) ; also on sheet 5
A8: U1.B7(DDR_A8) ; also on sheet 5
A9: U1.A5(DDR_A9) ; also on sheet 5
A10: U1.C8(DDR_A10) ; also on sheet 5
A11: U1.B6(DDR_A11) ; also on sheet 5
A12: U1.A4(DDR_A12) ; also on sheet 5
ADC_KEY: U1.F20(ADC_CH2) ; also on sheet 4
ADCDAT: U1.J19(I2S_SI) ; also on sheet 8
AV_DET: U1.M20(SC_B1) ; also on sheet 8
BA0: U1.C10(DDR_BA0) ; also on sheet 5
BA1: U1.C9(DDR_BA1) ; also on sheet 5
BA2: U1.B12(DDR_BA2) ; also on sheet 5
BATT_DET: U1.AA15(STRIG0) ; also on sheet 4
BCLK: U1.J22(I2S_CLK) ; also on sheet 8
CAS#: U1.B9(DDR_CAS) ; also on sheet 5
CEC_CTRL: R27.2 U1.R11(CEC_CTRL_LINE)
CK: R21.1 ; also on sheet 5
CK#: R22.1 ; also on sheet 5
CKE: U1.B11(DDR_CKE) ; also on sheet 5
CMOS_HIS: U1.D17(SHSYNC) ; also on sheet 4
CMOS_PWDN: U1.K21(TIMER1) ; also on sheet 4
CMOS_RST: U1.Y15(STRIG1) ; also on sheet 4
CMOS_VIS: U1.E16(SVSYNC) ; also on sheet 4
COMPOSITE: U1.F2(IOR) ; also on sheet 8
COMS-DSP_CLK: R53.2 ; also on sheet 4
DACDAT: U1.J20(I2S_SO) ; also on sheet 8
DACLRC: U1.J21(I2S_WS) ; also on sheet 8
DM0: U1.C15(DDR_DM0) ; also on sheet 5
DM1: U1.B19(DDR_DM1) ; also on sheet 5
DQ0: U1.A14(DDR_DQ0) ; also on sheet 5
DQ1: U1.C14(DDR_DQ1) ; also on sheet 5
DQ2: U1.B13(DDR_DQ2) ; also on sheet 5
DQ3: U1.C13(DDR_DQ3) ; also on sheet 5
DQ4: U1.C12(DDR_DQ4) ; also on sheet 5
DQ5: U1.A13(DDR_DQ5) ; also on sheet 5
DQ6: U1.C16(DDR_DQ6) ; also on sheet 5
DQ7: U1.B14(DDR_DQ7) ; also on sheet 5
DQ8: U1.A17(DDR_DQ8) ; also on sheet 5
DQ9: U1.A19(DDR_DQ9) ; also on sheet 5
DQ10: U1.B16(DDR_DQ10) ; also on sheet 5
DQ11: U1.C17(DDR_DQ11) ; also on sheet 5
DQ12: U1.C18(DDR_DQ12) ; also on sheet 5
DQ13: U1.A16(DDR_DQ13) ; also on sheet 5
DQ14: U1.A20(DDR_DQ14) ; also on sheet 5
DQ15: U1.B17(DDR_DQ15) ; also on sheet 5
DQS0: U1.A15(DDR_DQS0) ; also on sheet 5
DQS0#: U1.B15(DDR_~{DQS0}) ; also on sheet 5
DQS1: U1.A18(DDR_DQS1) ; also on sheet 5
DQS1#: U1.B18(DDR_~{DQS1}) ; also on sheet 5
DSP-COMS_CLK: C65.1 R54.2 ; also on sheet 4
HDMI_CH0_M: L11.2 U1.Y6(HDMI_CH0M)
HDMI_CH0_P: L11.3 U1.AA6(HDMI_CH0P)
HDMI_CH1_M: L10.2 U1.AA7(HDMI_CH1M)
HDMI_CH1_P: L10.3 U1.Y7(HDMI_CH1P)
HDMI_CH2_M: L9.2 U1.AB6(HDMI_CH2M)
HDMI_CH2_P: L9.3 U1.AB7(HDMI_CH2P)
HDMI_CLK_M: L12.2 U1.W6(HDMI_CLKM)
HDMI_CLK_P: L12.3 U1.W7(HDMI_CLKP)
HDMI_HOTPLUG: Q3.4 R39.2 U1.Y9(HDMI_HPD)
HDMISCL: Q12.S(SOURCE) R33.1 U1.AB9(IDC1_CLK)
HDMISCL_A: CN1.15(SCL) Q12.D(DRAIN) R34.1
HDMISDA: Q16.S(SOURCE) R32.1 U1.AA9(IDC1_DATA)
HDMISDA_A: CN1.16(SDA) Q16.D(DRAIN) R35.1
I2C_SCK: R50.1 U1.H22(IDC_CLK) ; also on sheet 4 8
I2C_SDA: R49.1 U1.H21(IDC_DATA) ; also on sheet 4 8
IR_IN: U1.W16(IR_IN) ; also on sheet 4
JTAG_CLK: CN2.9 R43.2 U1.K4(JTAG_CLK)
JTAG_RST: CN2.10 R42.2 U1.G2(JTAG_RST_L)
JTAG_TDI: CN2.7 R45.2 U1.H1(JTAG_TDI)
JTAG_TDO: CN2.6 U1.J1(JTAG_TDO)
JTAG_TMS: CN2.8 R44.2 U1.H2(JTAG_TEST_MODE)
KEY_DISP: Q14.B(IN) U1.AA18(CF_PULL_CTL) ; also on sheet 4
KEY_ENTER: U1.P22(SC_A4) ; also on sheet 4
KEY_MENU: U1.W17(CD2) ; also on sheet 4
KEY_PLAYBACK: U1.M22(SC_C4) ; also on sheet 4
KEY_R1: U1.W14(SD12) ; also on sheet 4
KEY_R2: U1.AB13(SD13) ; also on sheet 4
KEY_R3: U1.AA14(SD14) ; also on sheet 4
KEY_R4: U1.V14(SD15) ; also on sheet 4
KEY_REC: U1.AB15(SD16) ; also on sheet 4
KEY_SHUTTER1: U1.L19(SC_C0) ; also on sheet 4
KEY_SHUTTER2: U1.L20(SC_C1) ; also on sheet 4
KEY_ZOOM_IN: U1.M21(SC_C3) ; also on sheet 4
KEY_ZOOM_OUT: U1.L21(SC_C2) ; also on sheet 4
LCD-ROT-DET: U1.K19(TIMER2) ; also on sheet 4
LCD_CLK: LC6.E(OUT) U1.K2(VD_CLK)
LCD_EN: U1.G22(SSIO_EN1) ; also on sheet 4
LCD_HSYNC: LC6.F(OUT) U1.J2(VD_HSYNC)
LCD_OUT0: LC5.H(OUT) R13.2 U1.Y8(VD_OUT7)
LCD_OUT1: LC5.G(OUT) R14.2 R126.2 U1.M2(VD_OUT6)
LCD_OUT2: LC5.F(OUT) R15.2 R123.2 U1.M1(VD_OUT5)
LCD_OUT3: LC5.E(OUT) R16.2 R31.2 U1.L4(VD_OUT4)
LCD_OUT4: LC4.H(OUT) R17.2 U1.L3(VD_OUT3)
LCD_OUT5: LC4.G(OUT) R18.2 U1.L2(VD_OUT2)
LCD_OUT6: LC4.F(OUT) R19.2 U1.K3(VD_OUT1)
LCD_OUT7: LC4.E(OUT) R20.2 U1.L1(VD_OUT0)
LCD_SCK: U1.J18(SSIO_CLK) ; also on sheet 4
LCD_SDA: U1.G21(SSIO_MOSI) ; also on sheet 4
LCD_VSYNC: LC6.G(OUT) U1.K1(VD_VSYNC)
LCDA_CLK: C147.2 LC6.A(IN) ; also on sheet 4
LCDA_HSYNC: LC6.B(IN) ; also on sheet 4
LCDA_OUT0: LC5.D(IN) ; also on sheet 4
LCDA_OUT1: LC5.C(IN) ; also on sheet 4
LCDA_OUT2: LC5.B(IN) ; also on sheet 4
LCDA_OUT3: LC5.A(IN) ; also on sheet 4
LCDA_OUT4: LC4.D(IN) ; also on sheet 4
LCDA_OUT5: LC4.C(IN) ; also on sheet 4
LCDA_OUT6: LC4.B(IN) ; also on sheet 4
LCDA_OUT7: LC4.A(IN) ; also on sheet 4
LCDA_VSYNC: LC6.C(IN) ; also on sheet 4
LCDBL_CNT: U1.K20(SC_B2) ; also on sheet 4
LCDDET: U1.L22(TIMER0) ; also on sheet 4
LCDV33: LC6.H(OUT) ; also on sheet 4
LED_BUSY_nCNT: U1.Y16(SD18) ; also on sheet 4
LED_POWER_nCNT: U1.W15(SD17) ; also on sheet 4
LED_SELF: U1.F22(STSCHG) ; also on sheet 4
MACRO_nDET: U1.N20(SC_A0) ; also on sheet 4
MCLK: U1.K22(CLK_AU) ; also on sheet 8
NAND_CE1: U1.H19(SSIO_EN0) ; also on sheet 6
NAND_WP: U1.V20(WP) ; also on sheet 6
ODT: U1.B10(DDR_ODT) ; also on sheet 5
POWER OFF: U1.N21(SC_B0) ; also on sheet 7
PWR_DET: U1.G20(PWRCYC) ; also on sheet 7
RAS#: U1.A10(DDR_RAS) ; also on sheet 5
RESET: R121.2 ; also on sheet 6 7
SD0: U1.Y12(SD0) ; also on sheet 4
SD1: U1.Y11(SD1) ; also on sheet 4
SD2: U1.W12(SD2) ; also on sheet 4
SD3: U1.AB10(SD3) ; also on sheet 4
SD4: U1.AA11(SD4) ; also on sheet 4
SD5: U1.Y13(SD5) ; also on sheet 4
SD6: U1.AA12(SD6) ; also on sheet 4
SD7: U1.W13(SD7) ; also on sheet 4
SD8: U1.V13(SD8) ; also on sheet 4
SD9: U1.AB12(SD9) ; also on sheet 4
SD10: U1.Y14(SD10) ; also on sheet 4
SD11: U1.AA13(SD11) ; also on sheet 4
SD_POWER_CNT: U1.K18(SC_B4) ; also on sheet 6
SMIO0: U1.Y21(SMIO_0) ; also on sheet 6
SMIO1: U1.W20(SMIO_1) ; also on sheet 6
SMIO3: C59.1 R47.2 ; also on sheet 6
SMIO4: U1.V21(SMIO_4) ; also on sheet 6
SMIO5: U1.T20(SMIO_5) ; also on sheet 6
SMIO6: U1.R19(SMIO_6) ; also on sheet 6
SMIO15: U1.V18(SMIO_15) ; also on sheet 6
SMIO19: U1.AB18(SMIO_19) ; also on sheet 6
SMIO20: U1.AA16(SMIO_20) ; also on sheet 6
SMIO21: U1.AB17(SMIO_21) ; also on sheet 6
SMIO22: U1.AB22(SMIO_22) ; also on sheet 6
SMIO23: U1.AB20(SMIO_23) ; also on sheet 6
SMIO24: U1.U19(SMIO_24) ; also on sheet 6
SMIO25: U1.AA20(SMIO_25) ; also on sheet 6
SMIO26: U1.T19(SMIO_26) ; also on sheet 6
SMIO27: U1.W18(SMIO_27) ; also on sheet 6
SMIO28: U1.AA17(SMIO_28) ; also on sheet 6
SMIO29: U1.AB16(SMIO_29) ; also on sheet 6
SMIO30: U1.V22(SMIO_30) ; also on sheet 6
SMIO31: U1.R20(SMIO_31) ; also on sheet 6
SMIO32: U1.U21(SMIO_32) ; also on sheet 6
SMIO33: U1.T21(SMIO_33) ; also on sheet 6
UART0_RX: CN2.5 R41.1 U1.F21(UART_RX)
UART0_TX: CN2.4 R40.1 U1.E22(UART_TX)
USB_DET: Q14.E(GND) U1.N2(DETECT_VBUS) ; also on sheet 8
USBDN: U1.T1(USB_DM) ; also on sheet 8
USBDP: U1.T2(USB_DP) ; also on sheet 8
VA12: C23.B(OUT) C30.2 C41.2 C50.2 C53.2 U1.E11(VDD_DLL) U1.P4(USB_VDDC) U1.V6(HDMI_PLL_VDD) U1.V11(VDDA12_PLL)
VA18: C25.2 C27.2 C33.B(OUT) C35.2 U1.D6(DDR_VDDA) U1.E8(DDR_VDDA) U1.E12(DDR_VDDA) U1.E15(DDR_VDDA)
VA25: C22.B(OUT) C51.2 C54.2 C55.2 C56.2 C57.2 C63.2 U1.B4(DAC_DHVDD) U1.D18(ADC_REF) U1.E17(ADC_AVDD) U1.G5(DAC_AHVDD) U1.H4(DAC_AHVDD) U1.P2(USB_VDD25) U1.W11(VDDA25_PLL)
VA33: C3.2 C6.2 C9.2 C12.2 C15.2 C49.2 C52.2 C60.2 C61.2 R2.2 R28.1 R29.1 U1.H5(VDD33) U1.H18(VDD33) U1.J5(VDD33) U1.K5(VDD33) U1.L5(VDD33) U1.L18(VDD33) U1.M18(VDD33) U1.N18(VDD33) U1.R4(USB_HVDD_T) U1.R5(USB_HVDD_T) U1.R8(VDD33) U1.R9(VDD33) U1.R10(VDD33) U1.U18(VDD33) U1.V19(VDD33)
VCLKI: C64.2 R56.2 U1.W9(XIN) Y2.1
VCLKO: C66.1 R56.1 U1.W10(XOUT) Y2.3
VD12: C1.2 C4.2 C7.2 C10.2 C13.2 C16.2 C17.2 C18.2 C19.2 C20.2 C21.2 C23.A(IN) C24.2 C26.2 C28.2 C29.2 C31.2 U1.AA1(VDD) U1.AA2(VDD) U1.AA4(VDD) U1.AB1(VDD) U1.AB5(VDD) U1.E5(DAC_DVDD) U1.E6(DDR_VDD12) U1.E10(DDR_VDD12) U1.E13(DDR_VDD12) U1.H9(VDD) U1.H10(VDD) U1.H13(VDD) U1.H14(VDD) U1.H15(VDD) U1.J8(VDD) U1.J15(VDD) U1.K8(VDD) U1.K15(VDD) U1.L8(VDD) U1.L15(VDD) U1.M8(VDD) U1.M15(VDD) U1.N8(VDD) U1.N15(VDD) U1.P15(VDD) U1.R12(VDD) U1.R13(VDD) U1.R14(VDD) U1.R15(VDD) U1.U1(VDD) U1.U2(VDD) U1.U3(VDD) U1.U5(VDD) U1.V1(VDD) U1.V2(VDD) U1.V3(VDD) U1.V4(VDD) U1.W1(VDD) U1.W2(VDD) U1.W3(VDD) U1.W4(VDD) U1.Y1(VDD) U1.Y2(VDD) U1.Y4(VDD) ; also on sheet 7
VD18: C2.2 C5.2 C8.2 C11.2 C14.2 C33.A(IN) C34.1 C40.2 C144.B(OUT) R23.1 U1.D5(DDR_VDDQ) U1.D7(DDR_VDDQ) U1.D8(DDR_VDDQ) U1.D9(DDR_VDDQ) U1.D10(DDR_VDDQ) U1.D11(DDR_VDDQ) U1.D12(DDR_VDDQ) U1.D13(DDR_VDDQ) U1.D15(DDR_VDDQ) U1.E7(DDR_VDDQ) U1.E9(DDR_VDDQ) U1.E14(DDR_VDDQ)
VD25: C22.A(IN) C42.2 U1.V8(HDMI_VDDA) U1.W8(HDMI_VDDA) ; also on sheet 4
VD_OUT8: R12.2 U1.M5(VD_OUT8)
VD_OUT9: R11.2 U1.M4(VD_OUT9)
VD_OUT10: R4.2 R10.2 U1.N1(VD_OUT10)
VD_OUT11: R9.2 U1.N3(VD_OUT11)
VD_OUT12: R8.2 U1.P1(VD_OUT12)
VD_OUT13: R7.2 U1.N5(VD_OUT13)
VD_OUT14: R6.2 U1.P3(VD_OUT14)
VD_OUT15: R5.2 U1.M3(VD_OUT15)
VRTC: D11.C R30.1 R38.2 U1.AA3(PWC_RTC_CP)
WE#: U1.C11(DDR_WE) ; also on sheet 5
WLED_CNT: U1.N22(SC_B3) ; also on sheet 7
XIN_USB: C146.1 R58.2 U1.R1(XIN_USB) Y3.1
XOUT_USB: C145.2 R58.1 U1.R2(XOUT_USB) Y3.3
N16788976: TP1.1 U1.A7(DDR_A13)
N16789626: C39.2 C40.1 R23.2 R24.1 U1.D14(DDR_VREF)
N16797218: R57.1 U1.J3(TEST_MODE)
N16797544: TP16.1 U1.AB14(SFIELD)
N16797606: R54.1 U1.D16(CLK_SI)
N16797939: C60.1 C61.1 U1.E3(COMP)
N16798018: C58.2 U1.F3(VREFOUT) U1.G4(VREFIN)
N16798451: R46.1 U1.R3(REXT)
N16798467: R48.1 U1.J4(RSET)
N16800413: C143.1 R121.1 U1.AA10(POR_L)
N17141688: R47.1 U1.R18(SMIO_3)
N17553588: C43.2 R26.1 U1.Y3(RTC_XI) Y1.1
N17553594: C44.2 R26.2 U1.W5(RTC_XO) Y1.4
N17681901: TP2.1 U1.C19(DDR_CALIBR)
N17684748: R55.1 U1.V12(VDDIO_VIN)
N17786089: CN1.14(CEC) R25.1 R27.1
N17801990: TP13.1 U1.G18(ADC_CH0)
N17801991: TP15.1 U1.D22(ADC_CH1)
N17823542: R28.2 U1.AB4(PWC_PC_VDD)
N17825107: TP3.1 U1.Y5(PWC_PC_REF)
N17825115: R29.2 U1.V5(PWC_WKUP)
N17825916: R30.2 U1.AA5(PWC_RSTINB)
N17825930: TP4.1 U1.AB2(PWC_RSTOB)
N17825931: TP5.1 U1.U4(PWC_PSEQ1)
N17825932: TP6.1 U1.AB3(PWC_PSEQ2)
N17825933: TP7.1 U1.T5(PWC_PSEQ3)
N17828775: Q2.1(IN) Q14.C(OUT)
N17828783: Q2.2(OUT) R4.1
N18557957: CN1.11(TDMS_CLK+) L12.4
N18557958: CN1.12(TDMS_CLK-) L12.1
N18557967: CN1.8(TDMS_D0+) L11.4
N18557968: CN1.9(TDMS_D0-) L11.1
N18557975: CN1.5(TDMS_D1+) L10.4
N18557976: CN1.6(TDMS_D1-) L10.1
N18557981: CN1.2(TDMS_D2+) L9.4
N18557982: CN1.3(TDMS_D2-) L9.1
N18583068: CN1.19(HOTPLUG) Q3.2
N22292749: R21.2 U1.A12(DDR_CK)
N22293685: R22.2 U1.A11(DDR_~{CK})
N22717159: R53.1 U1.AB11(SPCLK)
N23840610: C48.1 R38.1
N27060444: R36.1 U1.V7(HDMI_REXT)

Not connected (* = marked no-connect by the designer): CN1 17(NC)*; Q3 5*; U1 AA8(VD_PWM0) AA19(SMIO_11) AA21(SMIO_13) AA22(SMIO_40) AB8(VD_VVLD) AB19(SMIO_2) AB21(SMIO_16) F1(IOG) G1(IOB) H20(SSIO_MISO) M19(SC_A3)* N19(SC_A1)* P18(SMIO_43) P19(SMIO_34) P20(SMIO_38) P21(SMIO_45) R21(SMIO_42) R22(SC_A2)* T18(SMIO_35) T22(SMIO_44) U20(SMIO_41) U22(SMIO_39) V15(SD19)* V16(SMIO_17) V17(SMIO_14) W19(SMIO_12) W21(SMIO_7) W22(SMIO_37) Y10(VD_HVLD) Y17(SMIO_10) Y18(SMIO_9) Y19(SMIO_8) Y20(SMIO_18) Y22(SMIO_36); U3 4(NC)

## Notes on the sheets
sheet 1
- DVH517 R16 100K/5% , R31 OPEN
- DVH527 R16 OPEN , R31 100K/5%
- Samuang VD_OUT6 = 0 ,
  Hnnix VD_OUT6 = 1
- Put close to
  A2S chip
sheet 3
- Debug Conn.
- JTAG
- NAND_CE1
- NAND_R/B
- SD_CLK
- SD_CMD
- SD_CD
- SD_WP
- NAND_RE
- IDE_IOWR
- NAND_WE
- IDE_D0
- NAND_ALE
- IDE_D1
- NAND_D0
- IDE_D2
- NAND_D1
- IDE_D3
- NAND_D2
- NAND_D3
- IDE_D4
- IDE_D5
- NAND_D4
- IDE_D6
- NAND_D5
- IDE_D7
- NAND_D6
- IDE_D8
- NAND_D7
- IDE_D9
- NAND_CLE
- SD_D0
- IDE_D10
- IDE_D11
- SD_D1
- IDE_D12
- SD_D2
- IDE_D13
- SD_D3
- IDE_D14
